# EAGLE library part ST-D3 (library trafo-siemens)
TRANSFORMER
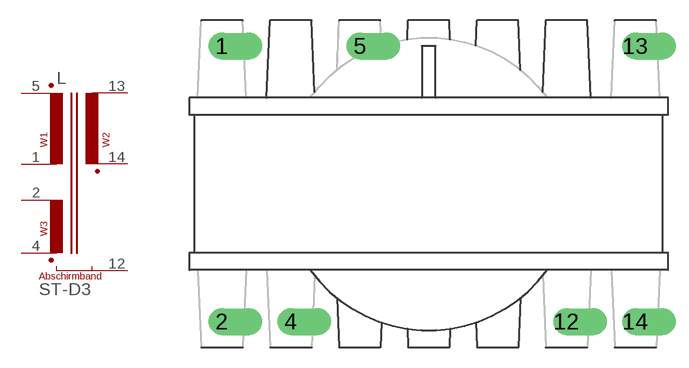
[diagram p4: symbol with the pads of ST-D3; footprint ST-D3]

Designator prefix L

## ST-D3  [ST-D3]
1  1E  pas
2  3E  pas
4  3A  pas
5  1A  pas
12  SCH  pas
13  2E  pas
14  2A  pas

## Footprint ST-D3 (pad centres in mm)
TRANSFORMER
drill 1.321 offset: 1 -15.24,10.16; 2 -15.24,-10.16; 4 -10.16,-10.16; 5 -5.08,10.16; 12 10.16,-10.16; 13 15.24,10.16; 14 15.24,-10.16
